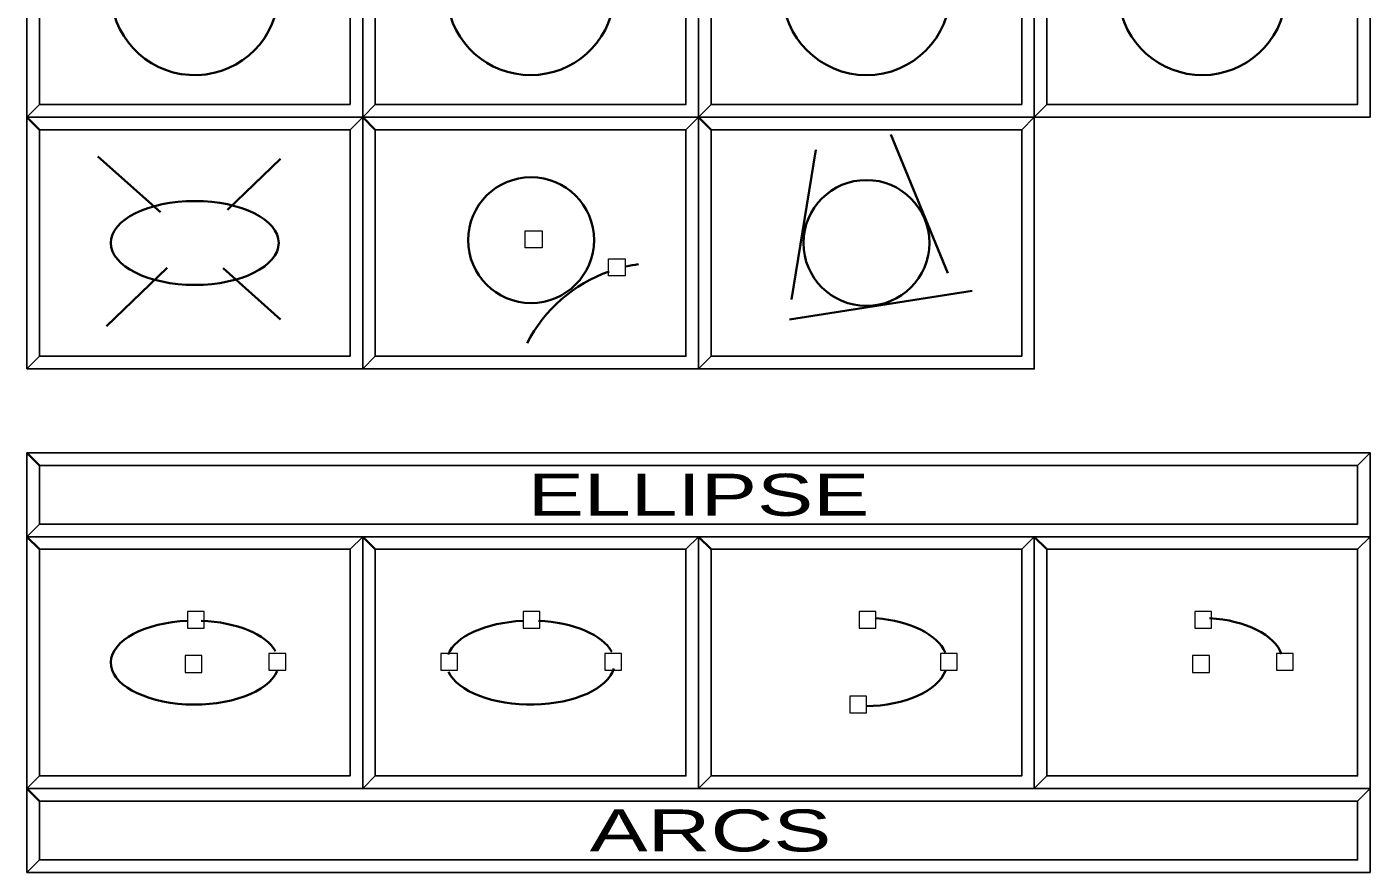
# Model space of a CAD drawing. Extents: x 95906.9 to 95918.9, y 90964.8 to 90972.9.
# Drawn here: x 95910.832 to 95912.432, y 90968.669 to 90969.669 of the extents above; entities that cross this region are included whole.
import ezdxf
from ezdxf.enums import TextEntityAlignment as Align

# ---------------------------------------------------------------- set-up
doc = ezdxf.new("R2010")
doc.units = 0
doc.header["$LTSCALE"] = 0.019
doc.linetypes.add('MEDIUM_DASHED', pattern=[4.5, 3, -1.5])
for name, color, linetype, lineweight in [('1', 7, 'Continuous', 25), ('11', 7, 'Continuous', 25), ('12', 7, 'Continuous', 25), ('17', 7, 'Continuous', 25), ('2', 7, 'Continuous', 13), ('3', 7, 'Continuous', 25), ('4', 7, 'Continuous', 35), ('6', 7, 'Continuous', 35), ('7', 7, 'Continuous', 35)]:
    doc.layers.add(name, color=color, linetype=linetype, lineweight=lineweight)

msp = doc.modelspace()

# ---------------------------------------------------------------- linework, layer by layer
at = {"layer": '1'}
for points in [[(95910.8318, 90969.5617), (95911.2318, 90969.5617), (95911.2318, 90969.8617), (95910.8318, 90969.8617)], [(95911.2318, 90969.5617), (95911.6318, 90969.5617), (95911.6318, 90969.8617), (95911.2318, 90969.8617)], [(95911.6318, 90969.5617), (95912.0318, 90969.5617), (95912.0318, 90969.8617), (95911.6318, 90969.8617)], [(95912.0318, 90969.5617), (95912.4318, 90969.5617), (95912.4318, 90969.8617), (95912.0318, 90969.8617)], [(95910.8318, 90969.2617), (95911.2318, 90969.2617), (95911.2318, 90969.5617), (95910.8318, 90969.5617)], [(95911.2318, 90969.2617), (95911.6318, 90969.2617), (95911.6318, 90969.5617), (95911.2318, 90969.5617)], [(95911.6318, 90969.2617), (95912.0318, 90969.2617), (95912.0318, 90969.5617), (95911.6318, 90969.5617)], [(95910.8318, 90969.0617), (95912.4318, 90969.0617), (95912.4318, 90969.1617), (95910.8318, 90969.1617)], [(95910.8318, 90968.7617), (95911.2318, 90968.7617), (95911.2318, 90969.0617), (95910.8318, 90969.0617)], [(95911.2318, 90968.7617), (95911.6318, 90968.7617), (95911.6318, 90969.0617), (95911.2318, 90969.0617)], [(95911.6318, 90968.7617), (95912.0318, 90968.7617), (95912.0318, 90969.0617), (95911.6318, 90969.0617)], [(95912.0318, 90968.7617), (95912.4318, 90968.7617), (95912.4318, 90969.0617), (95912.0318, 90969.0617)], [(95910.8318, 90968.6617), (95912.4318, 90968.6617), (95912.4318, 90968.7617), (95910.8318, 90968.7617)]]:
    msp.add_lwpolyline(points, close=True, dxfattribs=at)
at = {"layer": '11'}
for points in [[(95910.8468, 90969.5767), (95911.2168, 90969.5767), (95911.2168, 90969.8467), (95910.8468, 90969.8467)], [(95911.2468, 90969.5767), (95911.6168, 90969.5767), (95911.6168, 90969.8467), (95911.2468, 90969.8467)], [(95911.6468, 90969.5767), (95912.0168, 90969.5767), (95912.0168, 90969.8467), (95911.6468, 90969.8467)], [(95912.0468, 90969.5767), (95912.4168, 90969.5767), (95912.4168, 90969.8467), (95912.0468, 90969.8467)], [(95910.8468, 90969.2767), (95911.2168, 90969.2767), (95911.2168, 90969.5467), (95910.8468, 90969.5467)], [(95911.2468, 90969.2767), (95911.6168, 90969.2767), (95911.6168, 90969.5467), (95911.2468, 90969.5467)], [(95911.6468, 90969.2767), (95912.0168, 90969.2767), (95912.0168, 90969.5467), (95911.6468, 90969.5467)], [(95910.8468, 90968.7767), (95911.2168, 90968.7767), (95911.2168, 90969.0467), (95910.8468, 90969.0467)], [(95911.2468, 90968.7767), (95911.6168, 90968.7767), (95911.6168, 90969.0467), (95911.2468, 90969.0467)], [(95911.6468, 90968.7767), (95912.0168, 90968.7767), (95912.0168, 90969.0467), (95911.6468, 90969.0467)], [(95912.0468, 90968.7767), (95912.4168, 90968.7767), (95912.4168, 90969.0467), (95912.0468, 90969.0467)]]:
    msp.add_lwpolyline(points, close=True, dxfattribs=at)
at = {"layer": '12'}
for points in [[(95910.8468, 90969.5767), (95911.2168, 90969.5767), (95911.2168, 90969.8467), (95910.8468, 90969.8467)], [(95910.8468, 90968.7767), (95911.2168, 90968.7767), (95911.2168, 90969.0467), (95910.8468, 90969.0467)]]:
    msp.add_lwpolyline(points, close=True, dxfattribs=at)
at = {"layer": '17'}
for points in [[(95910.8468, 90969.0767), (95912.4168, 90969.0767), (95912.4168, 90969.1467), (95910.8468, 90969.1467)], [(95910.8468, 90968.6767), (95912.4168, 90968.6767), (95912.4168, 90968.7467), (95910.8468, 90968.7467)]]:
    msp.add_lwpolyline(points, close=True, dxfattribs=at)
at = {"layer": '2'}
for points in [[(95910.8318, 90969.8617), (95910.8318, 90969.5617), (95910.8468, 90969.5767), (95910.8468, 90969.8467), (95911.2168, 90969.8467), (95911.2318, 90969.8617)], [(95911.2318, 90969.8617), (95911.2318, 90969.5617), (95911.2468, 90969.5767), (95911.2468, 90969.8467), (95911.6168, 90969.8467), (95911.6318, 90969.8617)], [(95911.6318, 90969.8617), (95911.6318, 90969.5617), (95911.6468, 90969.5767), (95911.6468, 90969.8467), (95912.0168, 90969.8467), (95912.0318, 90969.8617)], [(95912.0318, 90969.8617), (95912.0318, 90969.5617), (95912.0468, 90969.5767), (95912.0468, 90969.8467), (95912.4168, 90969.8467), (95912.4318, 90969.8617)], [(95910.8318, 90969.5617), (95910.8318, 90969.2617), (95910.8468, 90969.2767), (95910.8468, 90969.5467), (95911.2168, 90969.5467), (95911.2318, 90969.5617)], [(95911.2318, 90969.5617), (95911.2318, 90969.2617), (95911.2468, 90969.2767), (95911.2468, 90969.5467), (95911.6168, 90969.5467), (95911.6318, 90969.5617)], [(95911.6318, 90969.5617), (95911.6318, 90969.2617), (95911.6468, 90969.2767), (95911.6468, 90969.5467), (95912.0168, 90969.5467), (95912.0318, 90969.5617)], [(95910.8318, 90969.1617), (95910.8318, 90969.0617), (95910.8468, 90969.0767), (95910.8468, 90969.1467), (95912.4168, 90969.1467), (95912.4318, 90969.1617)], [(95910.8318, 90969.0617), (95910.8318, 90968.7617), (95910.8468, 90968.7767), (95910.8468, 90969.0467), (95911.2168, 90969.0467), (95911.2318, 90969.0617)], [(95911.2318, 90969.0617), (95911.2318, 90968.7617), (95911.2468, 90968.7767), (95911.2468, 90969.0467), (95911.6168, 90969.0467), (95911.6318, 90969.0617)], [(95911.6318, 90969.0617), (95911.6318, 90968.7617), (95911.6468, 90968.7767), (95911.6468, 90969.0467), (95912.0168, 90969.0467), (95912.0318, 90969.0617)], [(95912.0318, 90969.0617), (95912.0318, 90968.7617), (95912.0468, 90968.7767), (95912.0468, 90969.0467), (95912.4168, 90969.0467), (95912.4318, 90969.0617)], [(95910.8318, 90968.7617), (95910.8318, 90968.6617), (95910.8468, 90968.6767), (95910.8468, 90968.7467), (95912.4168, 90968.7467), (95912.4318, 90968.7617)]]:
    msp.add_lwpolyline(points, close=True, dxfattribs=at)
at = {"layer": '3'}
for points in [[(95910.8318, 90969.5617), (95911.2318, 90969.5617), (95911.2318, 90969.8617), (95911.2168, 90969.8467), (95911.2168, 90969.5767), (95910.8468, 90969.5767)], [(95911.2318, 90969.5617), (95911.6318, 90969.5617), (95911.6318, 90969.8617), (95911.6168, 90969.8467), (95911.6168, 90969.5767), (95911.2468, 90969.5767)], [(95911.6318, 90969.5617), (95912.0318, 90969.5617), (95912.0318, 90969.8617), (95912.0168, 90969.8467), (95912.0168, 90969.5767), (95911.6468, 90969.5767)], [(95912.0318, 90969.5617), (95912.4318, 90969.5617), (95912.4318, 90969.8617), (95912.4168, 90969.8467), (95912.4168, 90969.5767), (95912.0468, 90969.5767)], [(95910.8318, 90969.2617), (95911.2318, 90969.2617), (95911.2318, 90969.5617), (95911.2168, 90969.5467), (95911.2168, 90969.2767), (95910.8468, 90969.2767)], [(95911.2318, 90969.2617), (95911.6318, 90969.2617), (95911.6318, 90969.5617), (95911.6168, 90969.5467), (95911.6168, 90969.2767), (95911.2468, 90969.2767)], [(95911.6318, 90969.2617), (95912.0318, 90969.2617), (95912.0318, 90969.5617), (95912.0168, 90969.5467), (95912.0168, 90969.2767), (95911.6468, 90969.2767)], [(95910.8318, 90969.0617), (95912.4318, 90969.0617), (95912.4318, 90969.1617), (95912.4168, 90969.1467), (95912.4168, 90969.0767), (95910.8468, 90969.0767)], [(95910.8318, 90968.7617), (95911.2318, 90968.7617), (95911.2318, 90969.0617), (95911.2168, 90969.0467), (95911.2168, 90968.7767), (95910.8468, 90968.7767)], [(95911.2318, 90968.7617), (95911.6318, 90968.7617), (95911.6318, 90969.0617), (95911.6168, 90969.0467), (95911.6168, 90968.7767), (95911.2468, 90968.7767)], [(95911.6318, 90968.7617), (95912.0318, 90968.7617), (95912.0318, 90969.0617), (95912.0168, 90969.0467), (95912.0168, 90968.7767), (95911.6468, 90968.7767)], [(95912.0318, 90968.7617), (95912.4318, 90968.7617), (95912.4318, 90969.0617), (95912.4168, 90969.0467), (95912.4168, 90968.7767), (95912.0468, 90968.7767)], [(95910.8318, 90968.6617), (95912.4318, 90968.6617), (95912.4318, 90968.7617), (95912.4168, 90968.7467), (95912.4168, 90968.6767), (95910.8468, 90968.6767)]]:
    msp.add_lwpolyline(points, close=True, dxfattribs=at)
at = {"layer": '4'}
for p, q in [((95910.8468, 90969.5467), (95910.8318, 90969.5617)), ((95911.2468, 90969.5467), (95911.2318, 90969.5617)), ((95911.6468, 90969.5467), (95911.6318, 90969.5617)), ((95910.8468, 90969.1467), (95910.8318, 90969.1617)), ((95910.8468, 90969.0467), (95910.8318, 90969.0617)), ((95911.2468, 90969.0467), (95911.2318, 90969.0617)), ((95911.6468, 90969.0467), (95911.6318, 90969.0617)), ((95912.0468, 90969.0467), (95912.0318, 90969.0617)), ((95910.8468, 90968.7467), (95910.8318, 90968.7617))]:
    msp.add_line(p, q, dxfattribs=at)
at = {"layer": '6'}
for p, q in [((95911.9289, 90969.3757), (95911.8607, 90969.541)), ((95911.7426, 90969.3442), (95911.7715, 90969.5226)), ((95911.74, 90969.3206), (95911.9578, 90969.3547))]:
    msp.add_line(p, q, dxfattribs=at)
at = {"layer": '6', "linetype": 'MEDIUM_DASHED'}
for p, q in [((95910.9162, 90969.5148), (95911.1339, 90969.3206)), ((95910.9267, 90969.3127), (95911.1339, 90969.5121))]:
    msp.add_line(p, q, dxfattribs=at)
at = {"layer": '6', "lineweight": 13}
for points in [[(95911.4455, 90969.406), (95911.4255, 90969.406), (95911.4255, 90969.426), (95911.4455, 90969.426)], [(95911.5445, 90969.3727), (95911.5245, 90969.3727), (95911.5245, 90969.3927), (95911.5445, 90969.3927)], [(95911.023, 90968.9526), (95911.043, 90968.9526), (95911.043, 90968.9726), (95911.023, 90968.9726)], [(95911.423, 90968.9526), (95911.443, 90968.9526), (95911.443, 90968.9726), (95911.423, 90968.9726)], [(95911.823, 90968.9526), (95911.843, 90968.9526), (95911.843, 90968.9726), (95911.823, 90968.9726)], [(95912.223, 90968.9526), (95912.243, 90968.9526), (95912.243, 90968.9726), (95912.223, 90968.9726)], [(95911.0204, 90968.9001), (95911.0404, 90968.9001), (95911.0404, 90968.9201), (95911.0204, 90968.9201)], [(95911.1201, 90968.9027), (95911.1401, 90968.9027), (95911.1401, 90968.9227), (95911.1201, 90968.9227)], [(95911.3248, 90968.9027), (95911.3448, 90968.9027), (95911.3448, 90968.9227), (95911.3248, 90968.9227)], [(95911.5201, 90968.9027), (95911.5401, 90968.9027), (95911.5401, 90968.9227), (95911.5201, 90968.9227)], [(95911.9201, 90968.9027), (95911.9401, 90968.9027), (95911.9401, 90968.9227), (95911.9201, 90968.9227)], [(95912.2204, 90968.9001), (95912.2404, 90968.9001), (95912.2404, 90968.9201), (95912.2204, 90968.9201)], [(95912.3201, 90968.9027), (95912.3401, 90968.9027), (95912.3401, 90968.9227), (95912.3201, 90968.9227)], [(95911.8119, 90968.8517), (95911.8319, 90968.8517), (95911.8319, 90968.8717), (95911.8119, 90968.8717)]]:
    msp.add_lwpolyline(points, close=True, dxfattribs=at)
at = {"layer": '6'}
for centre, radius in [((95911.8318, 90969.7117), 0.1), ((95911.4324, 90969.4151), 0.075), ((95911.8318, 90969.4117), 0.075)]:
    msp.add_circle(centre, radius, dxfattribs=at)
for centre, radius, start, end in [((95911.0318, 90969.7117), 0.1, 4.8874, 353.6041), ((95911.4318, 90969.7117), 0.1, 186.3938, 353.698), ((95912.2318, 90969.7117), 0.1, 185.8843, 354.917), ((95911.5848, 90969.2113), 0.1768, 109.6854, 152.699), ((95911.5848, 90969.2113), 0.1768, 98.0074, 102.8294)]:
    msp.add_arc(centre, radius, start, end, dxfattribs=at)
msp.add_ellipse((95911.0318, 90969.4117), major_axis=(0.1, 0), ratio=0.5, dxfattribs=at)
for centre, major_axis, ratio, start_param, end_param in [((95911.0318, 90968.9117), (0.1, 0), 0.5, 1.652145, 6.081781), ((95911.0318, 90968.9117), (0.1, 0), 0.5, 0.273628, 1.493467), ((95911.4318, 90968.9117), (0.1, 0), 0.5, 1.662997, 2.947365), ((95911.4318, 90968.9117), (0.1, 0), 0.5, 0.260759, 1.478137), ((95911.8286, 90968.9124), (-0.0993, 0), 0.53093, 3.360642, 4.563617), ((95912.2285, 90968.9124), (-0.0993, 0), 0.53093, 3.321217, 4.591689), ((95911.4318, 90968.9117), (0.1, 0), 0.5, 3.359628, 6.146211), ((95911.8286, 90968.9124), (-0.0993, 0), 0.53093, 1.599791, 2.939476)]:
    msp.add_ellipse(centre, major_axis=major_axis, ratio=ratio, start_param=start_param, end_param=end_param, dxfattribs=at)

# ---------------------------------------------------------------- texts
at = {"layer": '7'}
for s, width, p in [('        ELLIPSE        ', 1.5, (95911.6318, 90969.0867)), ('          ARCS         ', 1.55, (95911.6317, 90968.6867))]:
    msp.add_text(s, height=0.04999, dxfattribs=dict(at, width=width)).set_placement(p, align=Align.CENTER)

doc.saveas('drawing.dxf')
